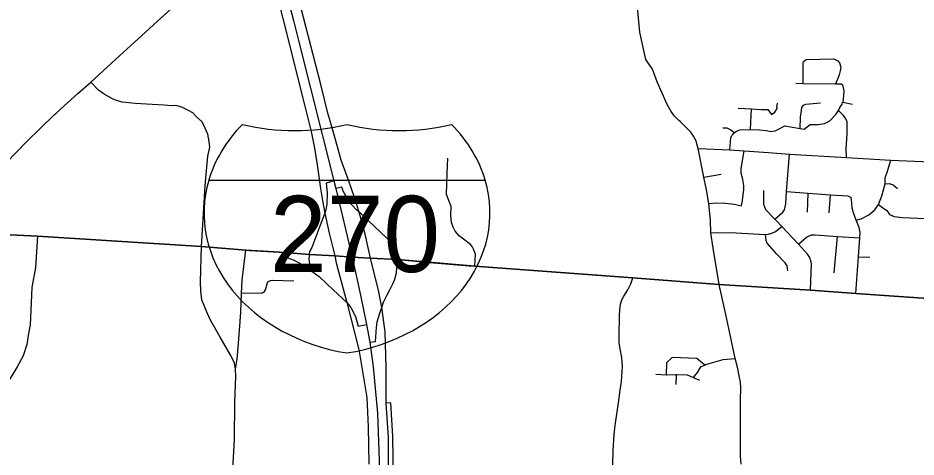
# Model space of a CAD drawing. Extents: x 1755200 to 1902939, y 644115 to 788070.
# Drawn here: x 1851175 to 1862951, y 746938 to 752702 of the extents above; entities that cross this region are included whole.
import ezdxf

# ---------------------------------------------------------------- set-up
doc = ezdxf.new("R2010")
doc.units = 0
for name, color, linetype in [('GM_X_City_Street', 7, 'Continuous'), ('GM_X_County_Road', 7, 'Continuous'), ('GM_X_Interchange_Ramps', 7, 'Continuous'), ('GM_X_Interstate_Route', 7, 'Continuous'), ('GM_X_Interstate_Shield', 7, 'Continuous'), ('GM_X_Township', 7, 'Continuous')]:
    doc.layers.add(name, color=color, linetype=linetype)

msp = doc.modelspace()

# ---------------------------------------------------------------- linework, layer by layer
at = {"layer": 'GM_X_City_Street'}
for points in [[(1859454, 752088), (1859408, 752155), (1859329, 752517), (1859255, 753310), (1859205, 753850), (1859199, 754339), (1859170, 754729)], [(1851672, 751448), (1851780, 751548), (1851958, 751708), (1852129, 751858), (1852504, 752203), (1852698, 752381), (1853053, 752701), (1853583, 753183), (1854276, 753823), (1854317, 753861)], [(1861476, 752131), (1861512, 752157), (1861872, 752166), (1861924, 752140), (1861946, 752114), (1861964, 752056), (1861954, 752006), (1861944, 751953), (1861924, 751909), (1861893, 751837)], [(1859856, 751343), (1859841, 751356), (1859784, 751411), (1859741, 751473), (1859687, 751564), (1859557, 751865), (1859494, 752031), (1859454, 752088)], [(1861469, 751843), (1861470, 752089), (1861470, 752111), (1861476, 752131)], [(1853639, 750599), (1853664, 750886), (1853690, 751006), (1853683, 751080), (1853665, 751175), (1853629, 751256), (1853589, 751337), (1853517, 751404), (1853467, 751455), (1853409, 751489), (1853323, 751529), (1853247, 751553), (1853190, 751550), (1853093, 751557), (1852936, 751567), (1852712, 751578), (1852541, 751597), (1852453, 751621), (1852405, 751644), (1852304, 751700), (1852229, 751753), (1852129, 751858)], [(1861374, 751844), (1861469, 751843), (1861893, 751837), (1861968, 751836), (1861985, 751822), (1862006, 751745), (1862001, 751681), (1861997, 751639), (1861992, 751595)], [(1860543, 751169), (1860564, 751194), (1860597, 751217), (1860641, 751231), (1860780, 751236), (1860897, 751233), (1860992, 751223), (1861048, 751212), (1861102, 751220), (1861140, 751237), (1861230, 751286), (1861433, 751249), (1861485, 751240), (1861564, 751304), (1861667, 751302), (1861752, 751316), (1861819, 751353), (1861898, 751433), (1861936, 751485), (1861953, 751526), (1861984, 751569), (1861988, 751595), (1861992, 751595), (1862118, 751571)], [(1860618, 751519), (1860793, 751510), (1860920, 751500), (1861007, 751502), (1861054, 751434), (1861100, 751465), (1861108, 751479), (1861129, 751513), (1861127, 751537), (1861136, 751581)], [(1861433, 751249), (1861435, 751401), (1861449, 751487), (1861455, 751527), (1861474, 751556), (1861504, 751568), (1861696, 751589)], [(1860780, 751236), (1860793, 751510)], [(1862049, 751272), (1862049, 751336), (1862032, 751378), (1862001, 751420), (1861936, 751485)], [(1860368, 749204), (1860290, 749682), (1860261, 749882), (1860255, 750045), (1860234, 750267), (1860205, 750447), (1860168, 750610), (1860095, 750987), (1860077, 751049), (1860066, 751089), (1860034, 751150), (1859996, 751202), (1859924, 751279), (1859856, 751343)], [(1860564, 751194), (1860519, 751233), (1860474, 751253), (1860416, 751256)], [(1862037, 750868), (1862033, 750982), (1862050, 751182), (1862049, 751272)], [(1860510, 750971), (1860521, 751129), (1860535, 751159), (1860543, 751169)], [(1860095, 750987), (1860510, 750971), (1860699, 750957), (1861015, 750936), (1861290, 750914), (1862037, 750868), (1862619, 750836), (1863241, 750810), (1864452, 750722), (1864480, 750720)], [(1857164, 749442), (1857173, 749601), (1857150, 749668), (1857130, 749702), (1857107, 749727), (1857015, 749799), (1856961, 749842), (1856908, 749905), (1856881, 749956), (1856858, 750017), (1856851, 750107), (1856855, 750227), (1856793, 750384), (1856802, 750666), (1856811, 750860)], [(1860658, 750237), (1860669, 750274), (1860679, 750341), (1860695, 750450), (1860691, 750503), (1860679, 750582), (1860658, 750665), (1860656, 750722), (1860666, 750779), (1860699, 750957)], [(1861099, 750062), (1861203, 750154), (1861225, 750185), (1861244, 750263), (1861252, 750422), (1861290, 750914)], [(1862166, 750047), (1862230, 750067), (1862334, 750119), (1862411, 750183), (1862457, 750253), (1862501, 750369), (1862545, 750524), (1862548, 750604), (1862576, 750691), (1862619, 750836)], [(1860168, 750610), (1860394, 750650)], [(1853581, 749702), (1853581, 749702), (1853631, 750497), (1853639, 750599)], [(1862545, 750524), (1862598, 750529), (1862653, 750513), (1862708, 750463)], [(1861125, 750034), (1861099, 750062), (1860983, 750185), (1860956, 750254), (1860953, 750310), (1860956, 750435)], [(1861252, 750422), (1861536, 750401), (1861831, 750379), (1862056, 750365), (1862102, 750343)], [(1861527, 750151), (1861536, 750401)], [(1860234, 750267), (1860334, 750277), (1860447, 750271), (1860571, 750256), (1860658, 750237)], [(1861813, 750142), (1861831, 750379)], [(1862184, 749391), (1862198, 749568), (1862212, 749816), (1862218, 749885), (1862204, 749952), (1862166, 750047), (1862130, 750142), (1862114, 750203), (1862109, 750276), (1862102, 750343)], [(1862457, 750253), (1862513, 750214), (1862566, 750173), (1862605, 750121), (1862664, 750094), (1862775, 750082), (1863070, 750070), (1863165, 750066)], [(1861564, 749535), (1861557, 749556), (1861527, 749602), (1861410, 749733), (1861191, 749965), (1861125, 750034)], [(1860261, 749882), (1860515, 749884), (1860979, 749861), (1861017, 749863), (1861062, 749877), (1861110, 749898), (1861191, 749965)], [(1850164, 749899), (1850178, 749898), (1851432, 749838), (1853581, 749702), (1854164, 749653), (1854211, 749651)], [(1851432, 749838), (1851405, 749428), (1851356, 749164), (1851343, 748864), (1851333, 748672), (1851315, 748559), (1851290, 748415), (1851241, 748265), (1851165, 748123), (1851097, 748013), (1851039, 747917), (1850993, 747855), (1850933, 747761), (1850903, 747696), (1850893, 747632), (1850888, 747450), (1850873, 747113), (1850864, 746855), (1850853, 746374), (1850846, 746224), (1850838, 745952), (1850846, 745706), (1850886, 745480), (1850900, 745441)], [(1861271, 749383), (1861259, 749449), (1861234, 749489), (1861122, 749607), (1861000, 749744), (1860984, 749781), (1860979, 749861)], [(1861410, 749733), (1861515, 749824), (1861582, 749853), (1861630, 749856), (1861920, 749832), (1862212, 749816)], [(1861879, 749358), (1861920, 749832)], [(1853922, 748347), (1853827, 748510), (1853700, 748733), (1853654, 748831), (1853585, 749004), (1853571, 749118), (1853568, 749238), (1853581, 749702)], [(1854028, 748094), (1854048, 748224), (1854064, 748375), (1854086, 748661), (1854095, 748841), (1854106, 749091), (1854114, 749260), (1854164, 749653)], [(1854211, 749651), (1854678, 749625), (1854995, 749599)], [(1854995, 749599), (1855330, 749578), (1855521, 749565)], [(1855521, 749565), (1855559, 749563), (1855798, 749550), (1856152, 749530), (1856204, 749525)], [(1862198, 749568), (1862346, 749560)], [(1856204, 749525), (1856569, 749494)], [(1856569, 749494), (1857091, 749448)], [(1857091, 749448), (1857164, 749442), (1858345, 749356)], [(1861567, 749127), (1861582, 749475), (1861570, 749517), (1861564, 749535)], [(1858345, 749356), (1859239, 749292), (1860368, 749204), (1861567, 749127), (1862160, 749085), (1862472, 749064), (1863172, 749017), (1865082, 748902), (1866053, 748847)], [(1862160, 749085), (1862184, 749391)], [(1854368, 749095), (1854381, 749095), (1854407, 749111), (1854422, 749135), (1854431, 749165), (1854442, 749211), (1854445, 749223), (1854459, 749241), (1854485, 749254), (1854518, 749260), (1854794, 749251)], [(1858967, 746454), (1858979, 747027), (1858993, 747230), (1858999, 747280), (1859010, 747385), (1859050, 747649), (1859073, 747815), (1859088, 747928), (1859095, 747999), (1859099, 748067), (1859100, 748127), (1859097, 748185), (1859092, 748246), (1859071, 748360), (1859059, 748442), (1859056, 748531), (1859063, 748801), (1859066, 748867), (1859071, 748906), (1859075, 748943), (1859094, 749001), (1859119, 749052), (1859171, 749131), (1859210, 749211), (1859239, 749292)], [(1860380, 749153), (1860368, 749204)], [(1854106, 749091), (1854368, 749095)], [(1860659, 746845), (1860651, 746952), (1860648, 747203), (1860649, 747307), (1860648, 747687), (1860652, 747847), (1860647, 747922), (1860638, 747982), (1860611, 748117), (1860581, 748234), (1860508, 748565), (1860459, 748809), (1860388, 749123), (1860380, 749153)], [(1853953, 746027), (1853963, 746238), (1854012, 747167), (1854020, 747660), (1854033, 747996), (1854028, 748094), (1854012, 748171), (1853967, 748271), (1853922, 748347)], [(1860180, 748145), (1860077, 748233), (1859754, 748244), (1859680, 748177), (1859674, 748012)], [(1860026, 747984), (1860044, 747998), (1860084, 748046), (1860114, 748100), (1860134, 748125), (1860180, 748145), (1860208, 748157), (1860420, 748220), (1860581, 748234)], [(1860114, 747945), (1860026, 747984), (1859954, 748014), (1859808, 748017), (1859797, 748017), (1859680, 748012), (1859674, 748012), (1859541, 748022)], [(1859805, 747889), (1859808, 748017)]]:
    msp.add_lwpolyline(points, dxfattribs=at)
at = {"layer": 'GM_X_County_Road'}
msp.add_lwpolyline([(1850625, 750413), (1850654, 750442), (1850761, 750538), (1851287, 751075), (1851650, 751428), (1851672, 751448)], dxfattribs=at)
at = {"layer": 'GM_X_Interchange_Ramps'}
for points in [[(1854414, 753631), (1854649, 752693), (1854933, 751563), (1855020, 751211), (1855063, 750991), (1855100, 750774), (1855144, 750461), (1855171, 750278), (1855198, 750140), (1855257, 749875), (1855330, 749578), (1855348, 749488), (1855487, 748967), (1855643, 748349), (1855749, 747720), (1855765, 747335), (1855776, 746845)], [(1856027, 746464), (1856034, 747197), (1856003, 747647), (1856002, 748113), (1855989, 748584), (1855944, 748902), (1855908, 749105), (1855798, 749550), (1855727, 749862), (1855651, 750152), (1855588, 750343), (1855509, 750573), (1855415, 750834), (1855363, 751011), (1855312, 751198), (1855239, 751451), (1855147, 751826), (1854886, 752844)], [(1855316, 750564), (1855214, 750535), (1855228, 750405), (1855226, 750257), (1855213, 750185), (1855198, 750140), (1855134, 749967), (1855030, 749690), (1854998, 749637), (1854995, 749599)], [(1856152, 749530), (1856151, 749564), (1856149, 749626), (1856139, 749662), (1856127, 749690), (1856110, 749715), (1856080, 749747), (1856014, 749808), (1855681, 750126), (1855651, 750152), (1855607, 750190), (1855513, 750294), (1855473, 750366), (1855441, 750428), (1855420, 750480), (1855343, 750461)], [(1854678, 749625), (1854675, 749568), (1854775, 749531), (1854870, 749483), (1855016, 749387), (1855123, 749306), (1855309, 749134), (1855487, 748967), (1855538, 748900), (1855600, 748781), (1855637, 748658), (1855743, 748680)], [(1854995, 749599), (1854993, 749576), (1854990, 749534), (1854992, 749502), (1854999, 749475), (1855014, 749445), (1855033, 749408), (1855016, 749387)], [(1855787, 748448), (1855862, 748457), (1855876, 748637), (1855887, 748712), (1855918, 748827), (1855944, 748902), (1855968, 748972), (1856018, 749068), (1856052, 749135), (1856092, 749212), (1856117, 749274), (1856137, 749356), (1856148, 749489), (1856152, 749530)], [(1856092, 746215), (1856094, 746250), (1856101, 746636), (1856091, 747210), (1856063, 747652), (1856003, 747647)]]:
    msp.add_lwpolyline(points, dxfattribs=at)
at = {"layer": 'GM_X_Interstate_Route'}
for points in [[(1854542, 753643), (1854543, 753636), (1854654, 753187), (1854786, 752668)], [(1854786, 752668), (1854857, 752389), (1855316, 750564), (1855343, 750461), (1855559, 749563)], [(1855559, 749563), (1855666, 749062), (1855743, 748680), (1855787, 748448), (1855832, 748122), (1855889, 747513), (1855913, 746894), (1855910, 746218), (1855867, 745511), (1855827, 744875), (1855781, 744012), (1855679, 742509)]]:
    msp.add_lwpolyline(points, dxfattribs=at)
at = {"layer": 'GM_X_Interstate_Shield'}
msp.add_line((1857302, 750570), (1853676, 750570), dxfattribs=at)
msp.add_line((1857302, 750570), (1853676, 750570), dxfattribs=at)
for centre, start_param, end_param in [((1855958, 750142), 2.47259, 2.911027), ((1854804, 753098), 4.415841, 5.008937), ((1856174, 753098), 4.415841, 5.008937), ((1855020, 750142), 0.230566, 0.669003), ((1855958, 750142), 2.911027, 4.511031), ((1855020, 750142), 4.913747, 6.513751)]:
    msp.add_ellipse(centre, major_axis=(2344, 0), ratio=0.8, start_param=start_param, end_param=end_param, dxfattribs=at)
at = {"layer": 'GM_X_Township'}
msp.add_lwpolyline([(1863172, 749017), (1862472, 749064), (1862160, 749085), (1861567, 749127), (1860368, 749204), (1859239, 749292), (1857164, 749442), (1856152, 749530), (1855788, 749550), (1855559, 749563), (1855330, 749578), (1854995, 749599), (1854678, 749625), (1854164, 749653), (1853581, 749702), (1851432, 749838), (1850178, 749898), (1848956, 749976), (1847649, 750064), (1846056, 750164), (1844025, 750293)], dxfattribs=at)

# ---------------------------------------------------------------- texts
at = {"layer": 'GM_X_Interstate_Shield'}
msp.add_text('270', height=1000, dxfattribs=at).set_placement((1854479, 749367))

doc.saveas('drawing.dxf')
